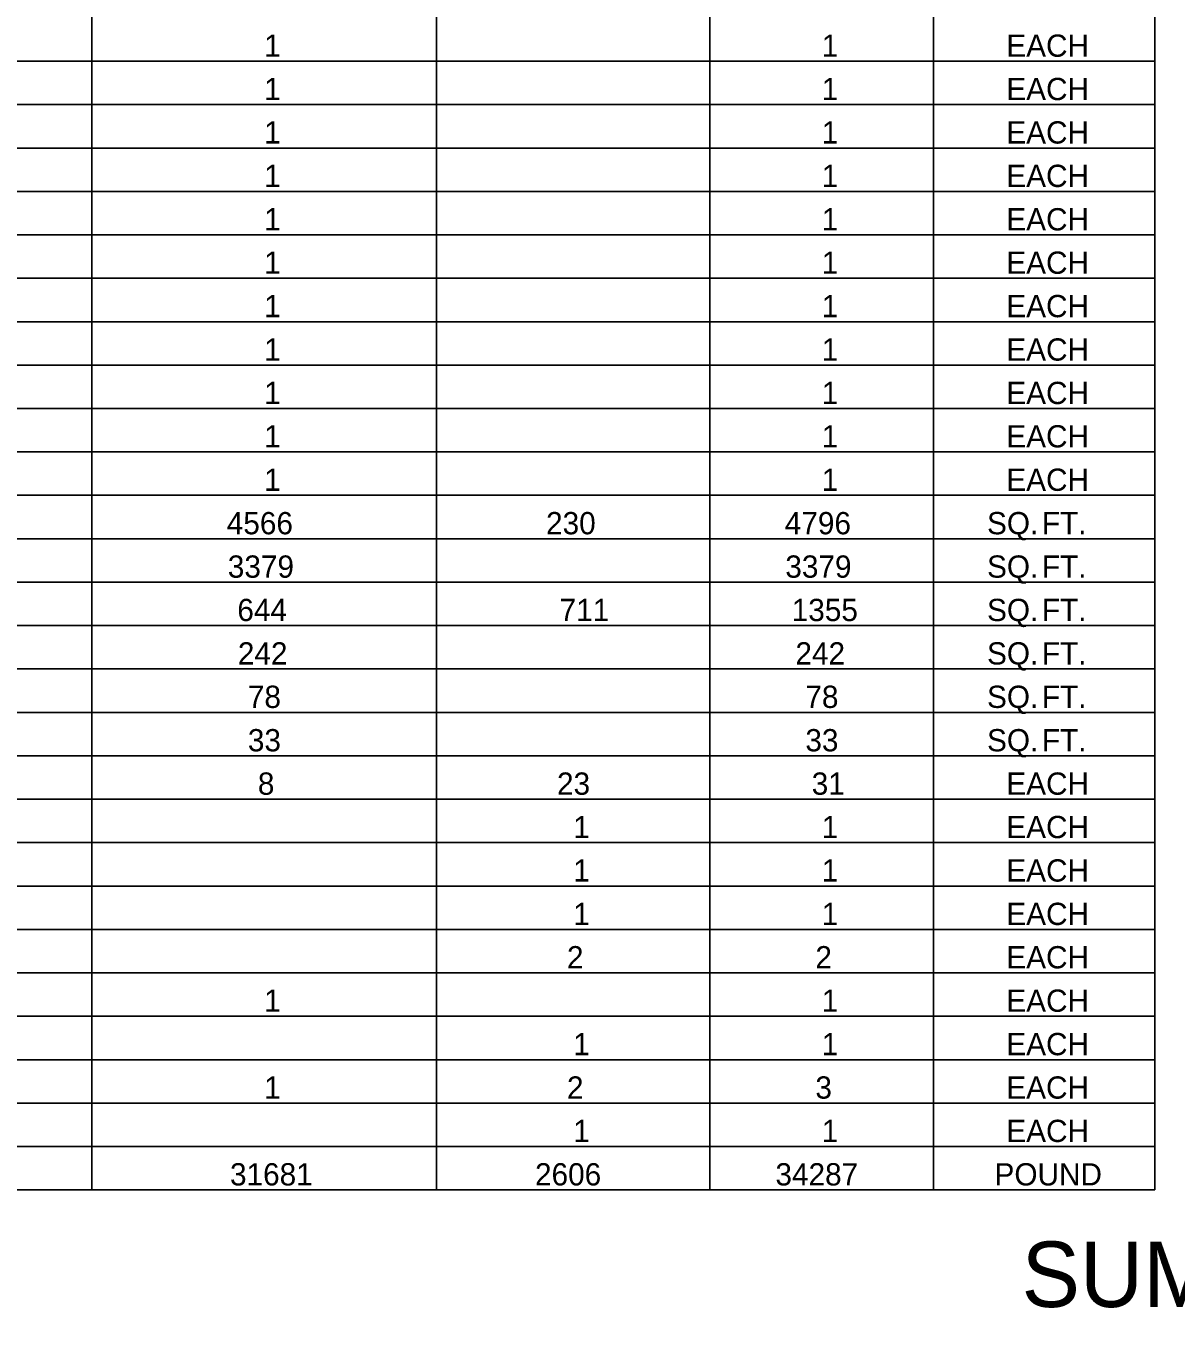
# Model space of a CAD drawing. Extents: x 1226603 to 1228117, y 151305 to 152343.
# Drawn here: x 1227709.6 to 1227929.3, y 151304.9 to 151552.9 of the extents above; entities that cross this region are included whole.
import ezdxf

# ---------------------------------------------------------------- set-up
doc = ezdxf.new("R2010")
doc.units = 0
doc.layers.add('R_Border Notes', color=7, linetype='Continuous')
doc.layers.add('R_Dimension', color=7, linetype='Continuous')

msp = doc.modelspace()

# ---------------------------------------------------------------- linework, layer by layer
at = {"layer": 'R_Dimension'}
for p, q in [((1227722.14, 151330.69), (1227722.14, 152231.95)), ((1227925.18, 151330.69), (1227925.18, 152231.95)), ((1227788.02, 151330.69), (1227788.02, 152217.86)), ((1227840.23, 151330.69), (1227840.23, 152217.86)), ((1227882.92, 151330.69), (1227882.92, 152217.86)), ((1227295.33, 151546.16), (1227925.18, 151546.16)), ((1227295.33, 151537.88), (1227925.18, 151537.88)), ((1227295.33, 151529.59), (1227925.18, 151529.59)), ((1227295.33, 151521.3), (1227925.18, 151521.3)), ((1227295.33, 151513.01), (1227925.18, 151513.01)), ((1227295.33, 151504.73), (1227925.18, 151504.73)), ((1227295.33, 151496.44), (1227925.18, 151496.44)), ((1227295.33, 151488.15), (1227925.18, 151488.15)), ((1227295.33, 151479.86), (1227925.18, 151479.86)), ((1227295.33, 151471.58), (1227925.18, 151471.58)), ((1227295.33, 151463.29), (1227925.18, 151463.29)), ((1227295.33, 151455), (1227925.18, 151455)), ((1227295.33, 151446.71), (1227925.18, 151446.71)), ((1227295.33, 151438.43), (1227925.18, 151438.43)), ((1227295.33, 151430.14), (1227925.18, 151430.14)), ((1227295.33, 151421.85), (1227925.18, 151421.85)), ((1227295.33, 151413.56), (1227925.18, 151413.56)), ((1227295.33, 151405.28), (1227925.18, 151405.28)), ((1227295.33, 151396.99), (1227925.18, 151396.99)), ((1227295.33, 151388.7), (1227925.18, 151388.7)), ((1227295.33, 151380.41), (1227925.18, 151380.41)), ((1227295.33, 151372.13), (1227925.18, 151372.13)), ((1227295.33, 151363.84), (1227925.18, 151363.84)), ((1227295.33, 151355.55), (1227925.18, 151355.55)), ((1227295.33, 151347.26), (1227925.18, 151347.26)), ((1227295.33, 151338.98), (1227925.18, 151338.98)), ((1227295.33, 151330.69), (1227925.18, 151330.69))]:
    msp.add_line(p, q, dxfattribs=at)

# ---------------------------------------------------------------- texts
at = {"layer": 'R_Border Notes'}
msp.add_text('SUMMARY OF QUANTITIES', height=12.5, dxfattribs=at).set_placement((1227899.76, 151308.33))
at = {"layer": 'R_Dimension'}
for s, p in [('1', (1227755.08, 151547.01)), ('1', (1227861.58, 151547.01)), ('EACH', (1227896.85, 151547.01)), ('1', (1227755.08, 151538.73)), ('1', (1227861.58, 151538.73)), ('EACH', (1227896.85, 151538.73)), ('1', (1227755.08, 151530.44)), ('1', (1227861.58, 151530.44)), ('EACH', (1227896.85, 151530.44)), ('1', (1227755.08, 151522.15)), ('1', (1227861.58, 151522.15)), ('EACH', (1227896.85, 151522.15)), ('1', (1227755.08, 151513.86)), ('1', (1227861.58, 151513.86)), ('EACH', (1227896.85, 151513.86)), ('1', (1227755.08, 151505.58)), ('1', (1227861.58, 151505.58)), ('EACH', (1227896.85, 151505.58)), ('1', (1227755.08, 151497.29)), ('1', (1227861.58, 151497.29)), ('EACH', (1227896.85, 151497.29)), ('1', (1227755.08, 151489)), ('1', (1227861.58, 151489)), ('EACH', (1227896.85, 151489)), ('1', (1227755.08, 151480.71)), ('1', (1227861.58, 151480.71)), ('EACH', (1227896.85, 151480.71)), ('1', (1227755.08, 151472.43)), ('1', (1227861.58, 151472.43)), ('EACH', (1227896.85, 151472.43)), ('1', (1227755.08, 151464.14)), ('1', (1227861.58, 151464.14)), ('EACH', (1227896.85, 151464.14)), ('4566', (1227747.94, 151455.85)), ('230', (1227808.93, 151455.85)), ('4796', (1227854.53, 151455.85)), ('SQ.', (1227893.16, 151455.85)), (' FT.', (1227902.06, 151455.85)), ('3379', (1227748.14, 151447.56)), ('3379', (1227854.63, 151447.56)), ('SQ.', (1227893.16, 151447.56)), (' FT.', (1227902.06, 151447.56)), ('644', (1227749.96, 151439.28)), ('711', (1227811.52, 151439.28)), ('1355', (1227855.85, 151439.28)), ('SQ.', (1227893.16, 151439.28)), (' FT.', (1227902.06, 151439.28)), ('242', (1227750.06, 151430.99)), ('242', (1227856.56, 151430.99)), ('SQ.', (1227893.16, 151430.99)), (' FT.', (1227902.06, 151430.99)), ('78', (1227751.97, 151422.7)), ('78', (1227858.46, 151422.7)), ('SQ.', (1227893.16, 151422.7)), (' FT.', (1227902.06, 151422.7)), ('33', (1227751.97, 151414.41)), ('33', (1227858.46, 151414.41)), ('SQ.', (1227893.16, 151414.41)), (' FT.', (1227902.06, 151414.41)), ('8', (1227753.88, 151406.13)), ('23', (1227811.02, 151406.13)), ('31', (1227859.67, 151406.13)), ('EACH', (1227896.85, 151406.13)), ('1', (1227814.13, 151397.84)), ('1', (1227861.58, 151397.84)), ('EACH', (1227896.85, 151397.84)), ('1', (1227814.13, 151389.55)), ('1', (1227861.58, 151389.55)), ('EACH', (1227896.85, 151389.55)), ('1', (1227814.13, 151381.26)), ('1', (1227861.58, 151381.26)), ('EACH', (1227896.85, 151381.26)), ('2', (1227812.92, 151372.98)), ('2', (1227860.37, 151372.98)), ('EACH', (1227896.85, 151372.98)), ('1', (1227755.08, 151364.69)), ('1', (1227861.58, 151364.69)), ('EACH', (1227896.85, 151364.69)), ('1', (1227814.13, 151356.4)), ('1', (1227861.58, 151356.4)), ('EACH', (1227896.85, 151356.4)), ('1', (1227755.08, 151348.11)), ('2', (1227812.92, 151348.11)), ('3', (1227860.37, 151348.11)), ('EACH', (1227896.85, 151348.11)), ('1', (1227814.13, 151339.83)), ('1', (1227861.58, 151339.83)), ('EACH', (1227896.85, 151339.83)), ('31681', (1227748.56, 151331.54)), ('2606', (1227806.82, 151331.54)), ('34287', (1227852.74, 151331.54)), ('POUND', (1227894.59, 151331.54))]:
    msp.add_text(s, height=4.25, dxfattribs=at).set_placement(p)

doc.saveas('drawing.dxf')
